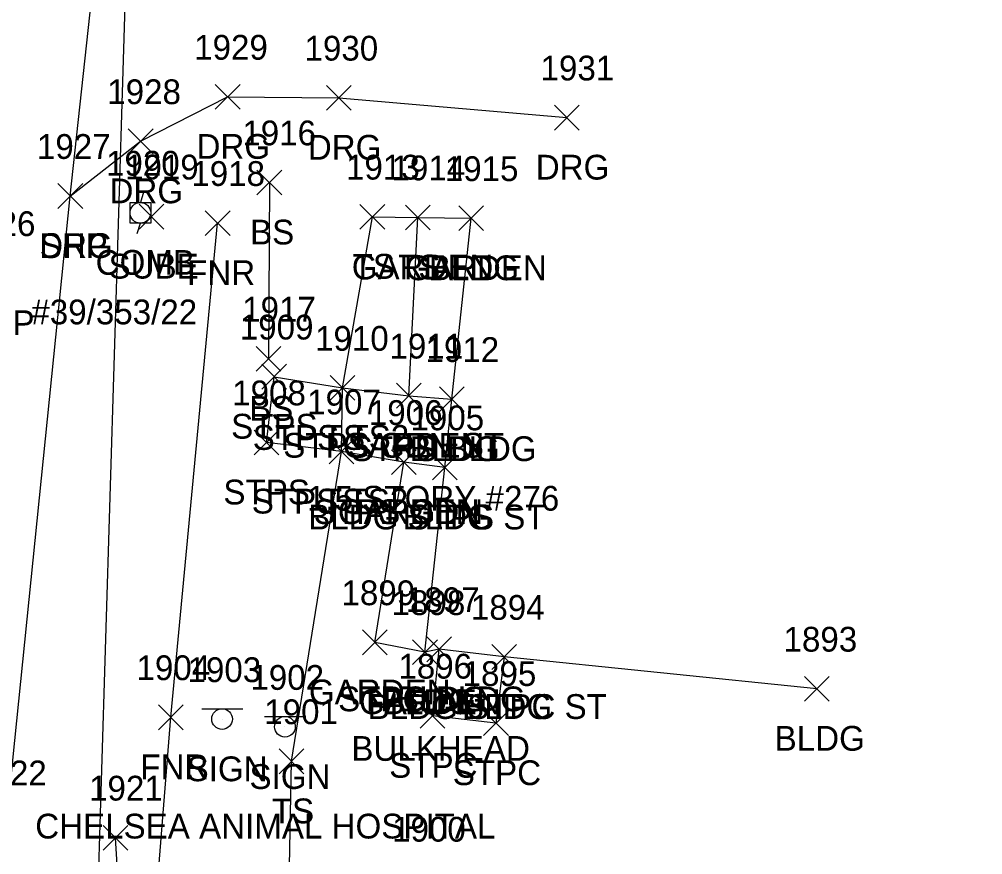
# Model space of a CAD drawing. Extents: x 1653908 to 1654393, y 539913 to 544256.
# Drawn here: x 1654097.1 to 1654174.9, y 541747 to 541814.4 of the extents above; entities that cross this region are included whole.
import ezdxf

# ---------------------------------------------------------------- set-up
doc = ezdxf.new("R2010")
doc.units = 0
for name, color, linetype in [('DCP', 7, 'Continuous'), ('L_A', 7, 'Continuous'), ('L_C', 7, 'Continuous'), ('L_I', 7, 'Continuous'), ('L_TIC', 7, 'Continuous'), ('LAPB', 7, 'Continuous'), ('LBC', 7, 'Continuous'), ('LBF', 7, 'Continuous'), ('LELB', 7, 'Continuous'), ('LFNC', 7, 'Continuous'), ('P_A', 7, 'Continuous'), ('P_I', 7, 'Continuous'), ('P_TIC', 7, 'Continuous'), ('PSP', 7, 'Continuous'), ('R_A', 7, 'Continuous'), ('R_I', 7, 'Continuous'), ('R_TIC', 7, 'Continuous'), ('RDG', 7, 'Continuous'), ('S_A', 7, 'Continuous'), ('S_C', 7, 'Continuous'), ('S_I', 7, 'Continuous'), ('SSGN', 7, 'Continuous'), ('U_A', 7, 'Continuous'), ('U_C', 7, 'Continuous'), ('U_I', 7, 'Continuous'), ('U_TIC', 7, 'Continuous'), ('UP', 7, 'Continuous')]:
    doc.layers.add(name, color=color, linetype=linetype)

msp = doc.modelspace()

# ---------------------------------------------------------------- linework, layer by layer
at = {"layer": 'DCP'}
msp.add_lwpolyline([(1654099.929, 541626.87), (1654106.243, 541833.218)], dxfattribs=at)
at = {"layer": 'L_TIC'}
for points in [[(1654116.332, 541800.244), (1654118.332, 541802.244)], [(1654118.332, 541800.244), (1654116.332, 541802.244)], [(1654124.649, 541797.481), (1654126.649, 541799.481)], [(1654126.649, 541797.481), (1654124.649, 541799.481)], [(1654128.319, 541797.42), (1654130.319, 541799.42)], [(1654130.319, 541797.42), (1654128.319, 541799.42)], [(1654128.319, 541797.42), (1654130.319, 541799.42)], [(1654130.319, 541797.42), (1654128.319, 541799.42)], [(1654132.621, 541797.359), (1654134.621, 541799.359)], [(1654134.621, 541797.359), (1654132.621, 541799.359)], [(1654132.621, 541797.359), (1654134.621, 541799.359)], [(1654134.621, 541797.359), (1654132.621, 541799.359)], [(1654112.158, 541796.966), (1654114.158, 541798.966)], [(1654114.158, 541796.966), (1654112.158, 541798.966)], [(1654116.263, 541786.016), (1654118.263, 541788.016)], [(1654118.263, 541786.016), (1654116.263, 541788.016)], [(1654116.727, 541784.572), (1654118.727, 541786.572)], [(1654118.727, 541784.572), (1654116.727, 541786.572)], [(1654122.234, 541783.664), (1654124.234, 541785.664)], [(1654124.234, 541783.664), (1654122.234, 541785.664)], [(1654122.234, 541783.664), (1654124.234, 541785.664)], [(1654124.234, 541783.664), (1654122.234, 541785.664)], [(1654127.59, 541783.036), (1654129.59, 541785.036)], [(1654129.59, 541783.036), (1654127.59, 541785.036)], [(1654127.59, 541783.036), (1654129.59, 541785.036)], [(1654129.59, 541783.036), (1654127.59, 541785.036)], [(1654131.065, 541782.758), (1654133.065, 541784.758)], [(1654133.065, 541782.758), (1654131.065, 541784.758)], [(1654131.065, 541782.758), (1654133.065, 541784.758)], [(1654133.065, 541782.758), (1654131.065, 541784.758)], [(1654116.105, 541779.26), (1654118.105, 541781.26)], [(1654118.105, 541779.26), (1654116.105, 541781.26)], [(1654122.156, 541778.526), (1654124.156, 541780.526)], [(1654124.156, 541778.526), (1654122.156, 541780.526)], [(1654122.156, 541778.526), (1654124.156, 541780.526)], [(1654124.156, 541778.526), (1654122.156, 541780.526)], [(1654127.192, 541777.674), (1654129.192, 541779.674)], [(1654129.192, 541777.674), (1654127.192, 541779.674)], [(1654127.192, 541777.674), (1654129.192, 541779.674)], [(1654129.192, 541777.674), (1654127.192, 541779.674)], [(1654130.496, 541777.245), (1654132.496, 541779.245)], [(1654132.496, 541777.245), (1654130.496, 541779.245)], [(1654130.496, 541777.245), (1654132.496, 541779.245)], [(1654132.496, 541777.245), (1654130.496, 541779.245)], [(1654124.857, 541763.127), (1654126.857, 541765.127)], [(1654126.857, 541763.127), (1654124.857, 541765.127)], [(1654128.898, 541762.331), (1654130.898, 541764.331)], [(1654130.898, 541762.331), (1654128.898, 541764.331)], [(1654128.898, 541762.331), (1654130.898, 541764.331)], [(1654130.898, 541762.331), (1654128.898, 541764.331)], [(1654130.049, 541762.566), (1654132.049, 541764.566)], [(1654132.049, 541762.566), (1654130.049, 541764.566)], [(1654130.049, 541762.566), (1654132.049, 541764.566)], [(1654132.049, 541762.566), (1654130.049, 541764.566)], [(1654135.299, 541761.947), (1654137.299, 541763.947)], [(1654137.299, 541761.947), (1654135.299, 541763.947)], [(1654135.299, 541761.947), (1654137.299, 541763.947)], [(1654137.299, 541761.947), (1654135.299, 541763.947)], [(1654160.539, 541759.38), (1654162.539, 541761.38)], [(1654162.539, 541759.38), (1654160.539, 541761.38)], [(1654108.377, 541757.079), (1654110.377, 541759.079)], [(1654110.377, 541757.079), (1654108.377, 541759.079)], [(1654129.499, 541757.203), (1654131.499, 541759.203)], [(1654131.499, 541757.203), (1654129.499, 541759.203)], [(1654134.629, 541756.606), (1654136.629, 541758.606)], [(1654136.629, 541756.606), (1654134.629, 541758.606)], [(1654118.126, 541753.525), (1654120.126, 541755.525)], [(1654120.126, 541753.525), (1654118.126, 541755.525)], [(1654103.902, 541747.359), (1654105.902, 541749.359)], [(1654105.902, 541747.359), (1654103.902, 541749.359)]]:
    msp.add_lwpolyline(points, dxfattribs=at)
at = {"layer": 'LAPB'}
for points in [[(1654128.59, 541784.036), (1654129.319, 541798.42), (1654133.621, 541798.359)], [(1654129.898, 541763.331), (1654125.857, 541764.127), (1654128.192, 541778.674)]]:
    msp.add_lwpolyline(points, dxfattribs=at)
at = {"layer": 'LBC'}
msp.add_lwpolyline([(1654161.539, 541760.38), (1654136.299, 541762.947), (1654131.049, 541763.566), (1654129.898, 541763.331), (1654131.496, 541778.245), (1654132.065, 541783.758), (1654133.621, 541798.359)], dxfattribs=at)
at = {"layer": 'LBF'}
for points in [[(1654131.496, 541778.245), (1654128.192, 541778.674), (1654123.156, 541779.526), (1654117.105, 541780.26), (1654117.727, 541785.572), (1654123.234, 541784.664), (1654128.59, 541784.036), (1654132.065, 541783.758)], [(1654136.299, 541762.947), (1654135.629, 541757.606), (1654130.499, 541758.203), (1654131.049, 541763.566)]]:
    msp.add_lwpolyline(points, dxfattribs=at)
at = {"layer": 'LELB'}
for points in [[(1654117.332, 541801.244), (1654117.263, 541787.016)], [(1654174.929, 541689.609), (1654139.554, 541695.908), (1654120.256, 541696.965), (1654118.265, 541709.402), (1654119.126, 541754.525), (1654123.156, 541779.526), (1654123.234, 541784.664), (1654125.649, 541798.481), (1654129.319, 541798.42)], [(1654113.151, 541697.725), (1654111.77, 541703.068), (1654112.289, 541709.283), (1654112.002, 541717.804), (1654106.523, 541722.359), (1654104.902, 541748.359)]]:
    msp.add_lwpolyline(points, dxfattribs=at)
at = {"layer": 'LFNC'}
msp.add_lwpolyline([(1654155.601, 541709.237), (1654134.22, 541709.292), (1654118.265, 541709.402), (1654112.289, 541709.283), (1654105.122, 541709.613), (1654106.523, 541722.359), (1654109.377, 541758.079), (1654113.158, 541797.966)], dxfattribs=at)
at = {"layer": 'P_TIC'}
for points in [[(1654100.261, 541799.15), (1654102.261, 541801.15)], [(1654102.261, 541799.15), (1654100.261, 541801.15)]]:
    msp.add_lwpolyline(points, dxfattribs=at)
at = {"layer": 'PSP'}
msp.add_lwpolyline([(1654094.458, 541721.214), (1654096.104, 541749.586), (1654101.261, 541800.15), (1654104.956, 541834.324), (1654108.508, 541872.884), (1654110.153, 541890.734), (1654111.767, 541915.009), (1654113.741, 541937.092), (1654116.462, 541969.541), (1654117.65, 541994.217), (1654121.735, 542040.282), (1654126.757, 542081.182), (1654129.731, 542120.034), (1654133.658, 542152.736), (1654138.064, 542196.396), (1654141.276, 542231.97)], dxfattribs=at)
at = {"layer": 'R_TIC'}
for points in [[(1654112.963, 541807.155), (1654114.963, 541809.155)], [(1654114.963, 541807.155), (1654112.963, 541809.155)], [(1654121.95, 541807.084), (1654123.95, 541809.084)], [(1654123.95, 541807.084), (1654121.95, 541809.084)], [(1654140.353, 541805.481), (1654142.353, 541807.481)], [(1654142.353, 541805.481), (1654140.353, 541807.481)], [(1654105.939, 541803.567), (1654107.939, 541805.567)], [(1654107.939, 541803.567), (1654105.939, 541805.567)], [(1654100.261, 541799.15), (1654102.261, 541801.15)], [(1654102.261, 541799.15), (1654100.261, 541801.15)]]:
    msp.add_lwpolyline(points, dxfattribs=at)
at = {"layer": 'RDG'}
msp.add_lwpolyline([(1654101.261, 541800.15), (1654106.939, 541804.567), (1654113.963, 541808.155), (1654122.95, 541808.084), (1654141.353, 541806.481)], dxfattribs=at)
at = {"layer": 'SSGN'}
for p, q in [((1654111.869, 541758.774), (1654115.202, 541758.774)), ((1654116.944, 541758.149), (1654120.277, 541758.149)), ((1654113.516, 541757.94), (1654113.516, 541757.94)), ((1654118.591, 541757.316), (1654118.591, 541757.316))]:
    msp.add_line(p, q, dxfattribs=at)
for centre in [(1654113.516, 541757.94), (1654118.591, 541757.316)]:
    msp.add_circle(centre, 0.833, dxfattribs=at)
at = {"layer": 'U_TIC'}
for points in [[(1654106.815, 541797.489), (1654108.815, 541799.489)], [(1654108.815, 541797.489), (1654106.815, 541799.489)]]:
    msp.add_lwpolyline(points, dxfattribs=at)
at = {"layer": 'UP'}
for p, q in [((1654107.172, 541800.461), (1654106.922, 541799.628)), ((1654106.089, 541797.961), (1654106.089, 541799.628)), ((1654106.089, 541799.628), (1654107.755, 541799.628)), ((1654107.755, 541799.628), (1654107.755, 541797.961)), ((1654106.922, 541798.795), (1654106.922, 541798.795)), ((1654107.755, 541797.961), (1654106.089, 541797.961)), ((1654106.672, 541797.128), (1654106.922, 541797.961))]:
    msp.add_line(p, q, dxfattribs=at)
msp.add_circle((1654106.922, 541798.795), 0.833, dxfattribs=at)

# ---------------------------------------------------------------- texts
at = {"layer": 'L_A'}
for s, p in [('BS', (1654115.773, 541796.244)), ('TS', (1654124.058, 541793.481)), ('GARDEN', (1654123.988, 541793.42)), ('TS', (1654127.728, 541793.42)), ('GARDEN', (1654128.291, 541793.359)), ('BLDG', (1654130.212, 541793.359)), ('FNR', (1654110.693, 541792.966)), ('BS', (1654115.704, 541782.016)), ('STPS', (1654114.247, 541780.572)), ('STPS TS2', (1654115.99, 541779.664)), ('TS', (1654121.644, 541779.664)), ('STPS GDN ST', (1654118.456, 541779.036)), ('GARDEN', (1654123.259, 541779.036)), ('STPS BLDG', (1654123.899, 541778.758)), ('BLDG', (1654128.655, 541778.758)), ('STPS', (1654113.624, 541775.26)), ('STPS TS2', (1654115.912, 541774.526)), ('TS', (1654121.566, 541774.526)), ('BLDG STPS ST', (1654120.465, 541773.245)), ('STPS GDN', (1654120.925, 541773.674)), ('GARDEN', (1654122.862, 541773.674)), ('BLDG', (1654128.087, 541773.245)), ('GARDEN', (1654120.526, 541759.127)), ('STPC BLDG', (1654122.883, 541758.566)), ('GARDEN', (1654124.567, 541758.331)), ('BLDG', (1654126.488, 541758.331)), ('BLDG', (1654127.639, 541758.566)), ('BLDG STPC ST', (1654125.268, 541757.947)), ('BLDG', (1654132.89, 541757.947)), ('BLDG', (1654158.129, 541755.38)), ('FNR', (1654106.912, 541753.079)), ('STPC', (1654127.011, 541753.203)), ('STPC', (1654132.14, 541752.606)), ('TS', (1654117.535, 541749.525))]:
    msp.add_text(s, height=2, dxfattribs=at).set_placement(p)
at = {"layer": 'L_C'}
for s, p in [('1.5 STORY #276', (1654120.372, 541774.758)), ('BULKHEAD', (1654123.954, 541754.566))]:
    msp.add_text(s, height=2, dxfattribs=at).set_placement(p)
at = {"layer": 'L_I'}
for s, p in [('1916', (1654115.151, 541804.244)), ('1913', (1654123.523, 541801.481)), ('1914', (1654127.193, 541801.42)), ('1914', (1654127.193, 541801.42)), ('1915', (1654131.496, 541801.359)), ('1915', (1654131.496, 541801.359)), ('1918', (1654111.032, 541800.966)), ('1917', (1654115.138, 541790.016)), ('1909', (1654114.948, 541788.572)), ('1910', (1654121.022, 541787.664)), ('1910', (1654121.022, 541787.664)), ('1911', (1654127.031, 541787.036)), ('1911', (1654127.031, 541787.036)), ('1912', (1654129.939, 541786.758)), ('1912', (1654129.939, 541786.758)), ('1908', (1654114.333, 541783.26)), ('1907', (1654120.385, 541782.526)), ('1907', (1654120.385, 541782.526)), ('1906', (1654125.366, 541781.674)), ('1906', (1654125.366, 541781.674)), ('1905', (1654128.725, 541781.245)), ('1905', (1654128.725, 541781.245)), ('1899', (1654123.156, 541767.127)), ('1898', (1654127.205, 541766.331)), ('1898', (1654127.205, 541766.331)), ('1897', (1654128.356, 541766.566)), ('1897', (1654128.356, 541766.566)), ('1894', (1654133.607, 541765.947)), ('1894', (1654133.607, 541765.947)), ('1893', (1654158.846, 541763.38)), ('1904', (1654106.605, 541761.079)), ('1896', (1654127.752, 541761.203)), ('1895', (1654132.936, 541760.606)), ('1901', (1654116.921, 541757.525)), ('1921', (1654102.776, 541751.359)), ('1900', (1654127.245, 541748.042))]:
    msp.add_text(s, height=2, dxfattribs=at).set_placement(p)
at = {"layer": 'P_A'}
for s, p in [('SHP', (1654098.796, 541795.15)), ('RDP', (1654092.733, 541788.922))]:
    msp.add_text(s, height=2, dxfattribs=at).set_placement(p)
at = {"layer": 'P_I'}
for s, p in [('1927', (1654098.568, 541803.15)), ('1926', (1654092.497, 541796.922)), ('1922', (1654093.412, 541752.586))]:
    msp.add_text(s, height=2, dxfattribs=at).set_placement(p)
at = {"layer": 'R_A'}
for p in [(1654111.451, 541803.155), (1654120.438, 541803.084), (1654138.841, 541801.481), (1654104.427, 541799.567), (1654098.749, 541795.15)]:
    msp.add_text('DRG', height=2, dxfattribs=at).set_placement(p)
at = {"layer": 'R_I'}
for s, p in [('1929', (1654111.263, 541811.155)), ('1930', (1654120.171, 541811.084)), ('1931', (1654139.227, 541809.481)), ('1928', (1654104.246, 541807.567)), ('1927', (1654098.568, 541803.15))]:
    msp.add_text(s, height=2, dxfattribs=at).set_placement(p)
at = {"layer": 'S_A'}
for p in [(1654110.654, 541752.92), (1654115.729, 541752.296)]:
    msp.add_text('SIGN', height=2, dxfattribs=at).set_placement(p)
at = {"layer": 'S_C'}
msp.add_text('CHELSEA ANIMAL HOSPITAL', height=2, dxfattribs=at).set_placement((1654098.43, 541748.296))
at = {"layer": 'S_I'}
for s, p in [('1903', (1654110.725, 541760.92)), ('1902', (1654115.8, 541760.296))]:
    msp.add_text(s, height=2, dxfattribs=at).set_placement(p)
at = {"layer": 'U_A'}
for s, p in [('COMB', (1654103.308, 541793.795)), ('SUBE', (1654104.35, 541793.489))]:
    msp.add_text(s, height=2, dxfattribs=at).set_placement(p)
at = {"layer": 'U_C'}
msp.add_text('#39/353/22', height=2, dxfattribs=at).set_placement((1654098.119, 541789.795))
at = {"layer": 'U_I'}
for s, p in [('1920', (1654104.143, 541801.795)), ('1919', (1654105.681, 541801.489))]:
    msp.add_text(s, height=2, dxfattribs=at).set_placement(p)

doc.saveas('drawing.dxf')
